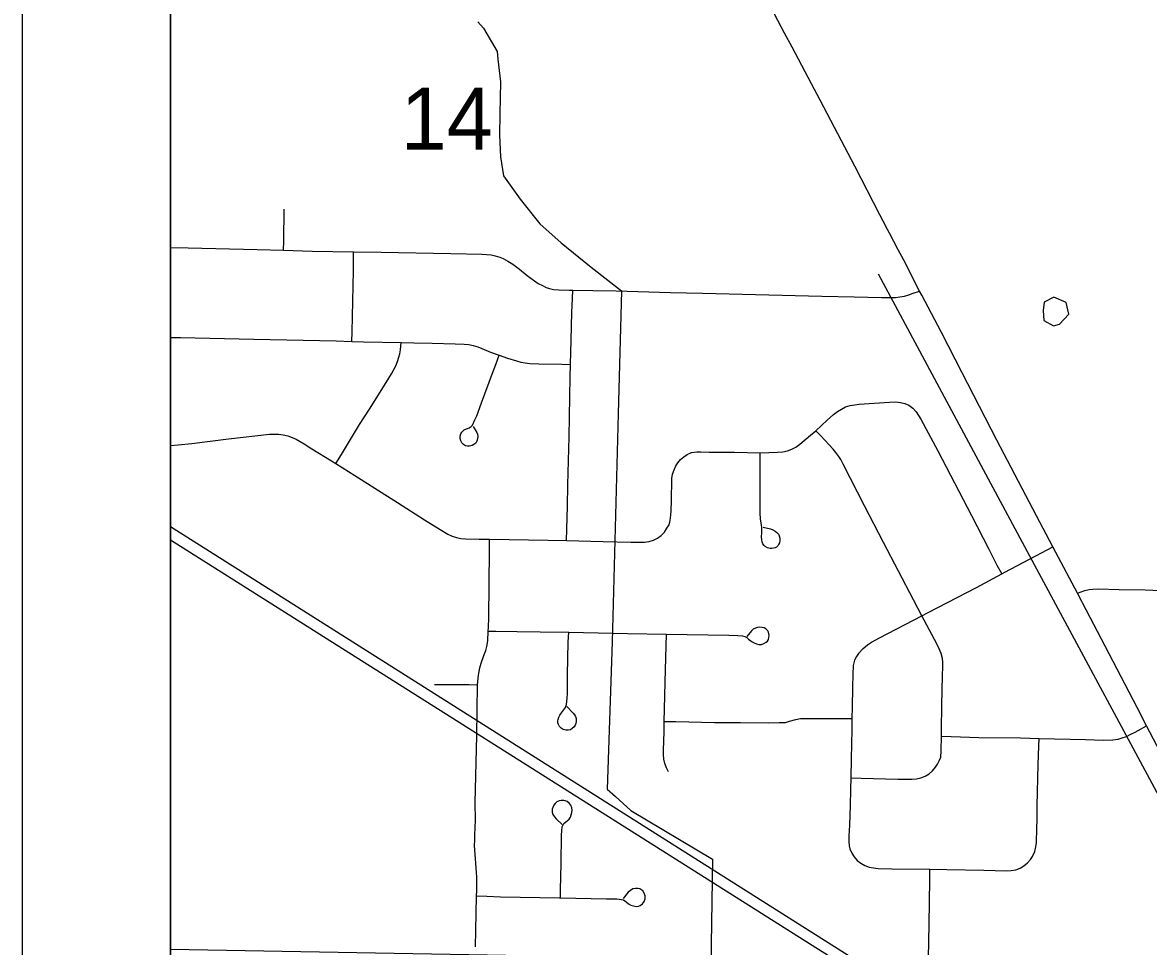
# Model space of a CAD drawing. Extents: x -59 to 43, y 0 to 22.
# Drawn here: x 23.417 to 24.177, y 18.366 to 18.99 of the extents above; entities that cross this region are included whole.
import ezdxf

# ---------------------------------------------------------------- set-up
doc = ezdxf.new("R2010")
doc.units = 0
for name, color, linetype in [('Default', 7, 'Continuous'), ('GM_X_City_Street', 7, 'Continuous'), ('GM_X_Interchange_Ramps', 7, 'Continuous'), ('GM_X_Minor_Lake', 7, 'Continuous'), ('GM_X_Minor_River', 7, 'Continuous'), ('GM_X_Rail_Line', 7, 'Continuous'), ('GM_X_Section_Text', 7, 'Continuous'), ('GM_X_State_Route', 7, 'Continuous'), ('SH_Data', 7, 'Continuous')]:
    doc.layers.add(name, color=color, linetype=linetype)

msp = doc.modelspace()

# ---------------------------------------------------------------- linework, layer by layer
at = {"layer": 'Default'}
msp.add_lwpolyline([(23.51667, 19.36712), (23.51667, 18.36457), (24.19635, 18.35229), (24.21701, 19.34715)], close=True, dxfattribs=at)
at = {"layer": 'GM_X_City_Street'}
for points in [[(23.59295, 18.83648), (23.59318, 18.84279), (23.59348, 18.86431)], [(23.51667, 18.83829), (23.52864, 18.83805), (23.57518, 18.83695), (23.59295, 18.83648), (23.6124, 18.83596), (23.64027, 18.83547), (23.65895, 18.83513), (23.70594, 18.83439), (23.72701, 18.83376), (23.73018, 18.83366), (23.73315, 18.83334), (23.73601, 18.83271), (23.73908, 18.83186), (23.74141, 18.83081), (23.74448, 18.82922), (23.74797, 18.8271), (23.75242, 18.82382), (23.75754, 18.81953), (23.76244, 18.81573), (23.76507, 18.81409), (23.76786, 18.81273), (23.77043, 18.81134), (23.77276, 18.8106), (23.77541, 18.80997), (23.7789, 18.80965), (23.78605, 18.8095), (23.78836, 18.80947), (23.80187, 18.80934), (23.81775, 18.80903), (23.85431, 18.80798), (23.87602, 18.80747), (23.9567, 18.80543), (23.97842, 18.80502), (23.99705, 18.80454), (24.00325, 18.80453), (24.00634, 18.80465), (24.00942, 18.80495), (24.01246, 18.80555), (24.01544, 18.80644), (24.01836, 18.80747), (24.02264, 18.80897)], [(23.63919, 18.77493), (23.63933, 18.78133), (23.64027, 18.8228), (23.64027, 18.82919), (23.64027, 18.83547)], [(23.7842, 18.64039), (23.78442, 18.64814), (23.78486, 18.66372), (23.78506, 18.67814), (23.78589, 18.71045), (23.78658, 18.75092), (23.78682, 18.75944), (23.78728, 18.77584), (23.78779, 18.79453), (23.78814, 18.80388), (23.78836, 18.80947)], [(23.51667, 18.77761), (23.52345, 18.77746), (23.57291, 18.77644), (23.62855, 18.77527), (23.63919, 18.77493), (23.64709, 18.77467), (23.67256, 18.7742), (23.6811, 18.77404), (23.69347, 18.77378), (23.70892, 18.77331), (23.7151, 18.77311), (23.71817, 18.77275), (23.72119, 18.77212), (23.72414, 18.77127), (23.72704, 18.77022), (23.73272, 18.76775), (23.73869, 18.76562), (23.74437, 18.76359), (23.75027, 18.76173), (23.75327, 18.761), (23.75629, 18.76044), (23.75933, 18.75999), (23.76551, 18.75969), (23.78097, 18.75951), (23.78682, 18.75944)], [(23.62823, 18.69245), (23.63207, 18.69864), (23.64424, 18.71875), (23.65101, 18.72922), (23.65941, 18.74235), (23.66585, 18.75303), (23.66877, 18.75852), (23.67, 18.76137), (23.67095, 18.76435), (23.67155, 18.76659), (23.6719, 18.76922), (23.67256, 18.7742)], [(23.72109, 18.71746), (23.7235, 18.71345), (23.72399, 18.71226), (23.7242, 18.71071), (23.72405, 18.70906), (23.7236, 18.70755), (23.7228, 18.70625), (23.72165, 18.7052), (23.7204, 18.70455), (23.7187, 18.7041), (23.71725, 18.70415), (23.71585, 18.7045), (23.71455, 18.70524), (23.71339, 18.70635), (23.7127, 18.70775), (23.71229, 18.7093), (23.71229, 18.7109), (23.71274, 18.7124), (23.71351, 18.71359), (23.71409, 18.71425), (23.71509, 18.7151), (23.71654, 18.71595), (23.71845, 18.71665), (23.71964, 18.71736), (23.72074, 18.71836), (23.72227, 18.7219), (23.72352, 18.72468), (23.72662, 18.73339), (23.73418, 18.75356), (23.73633, 18.75931), (23.73869, 18.76562)], [(23.91505, 18.69978), (23.92664, 18.70024), (23.93035, 18.70034), (23.93353, 18.70098), (23.93638, 18.70215), (23.93903, 18.70353), (23.94167, 18.70543), (23.94909, 18.71158), (23.95247, 18.71444), (23.9603, 18.72164), (23.96453, 18.72566), (23.96718, 18.72757), (23.96983, 18.72916), (23.97268, 18.73064), (23.97581, 18.73156), (23.97885, 18.73215), (23.98192, 18.73251), (24.00243, 18.73394), (24.00656, 18.73405), (24.00984, 18.73373), (24.01281, 18.73299), (24.01535, 18.73183), (24.018, 18.72992), (24.02033, 18.72728), (24.02351, 18.72241), (24.03495, 18.70103), (24.05763, 18.65742), (24.06939, 18.63466), (24.07479, 18.62387), (24.07829, 18.61804)], [(23.51667, 18.7046), (23.52187, 18.70499), (23.53115, 18.70592), (23.55578, 18.70914), (23.58351, 18.71219), (23.5866, 18.71232), (23.5897, 18.7122), (23.59278, 18.7118), (23.5958, 18.71112), (23.59873, 18.71012), (23.60155, 18.70882), (23.60693, 18.70574), (23.61213, 18.70236), (23.62532, 18.69424), (23.62823, 18.69245), (23.64107, 18.68431), (23.66989, 18.66607), (23.68823, 18.65446), (23.69871, 18.64784), (23.70404, 18.64464), (23.70683, 18.64331), (23.70978, 18.6424), (23.71283, 18.64189), (23.71593, 18.64164), (23.72522, 18.64139), (23.73203, 18.64128), (23.77173, 18.64064), (23.7842, 18.64039), (23.80894, 18.6399), (23.82753, 18.63943), (23.83683, 18.6393), (23.8399, 18.63972), (23.84285, 18.64068), (23.8456, 18.6421), (23.84808, 18.64395), (23.85026, 18.64615), (23.85203, 18.6487), (23.85344, 18.65114), (23.85428, 18.654), (23.85471, 18.65749), (23.85492, 18.66099), (23.85502, 18.66702), (23.85541, 18.68237), (23.85585, 18.68534), (23.85692, 18.68809), (23.85808, 18.69095), (23.85935, 18.69296), (23.86125, 18.69519), (23.86347, 18.69709), (23.8657, 18.69857), (23.86856, 18.69985), (23.87215, 18.70037), (23.8748, 18.70037), (23.88062, 18.70006), (23.88804, 18.70006), (23.89767, 18.70018), (23.91505, 18.69978)], [(23.9763, 18.4802), (23.98319, 18.47996), (24.00808, 18.4794), (24.0143, 18.47919), (24.01741, 18.47919), (24.02051, 18.47947), (24.02354, 18.48015), (24.02645, 18.48127), (24.0291, 18.48288), (24.03143, 18.48493), (24.03342, 18.48733), (24.03473, 18.48935), (24.036, 18.49157), (24.03695, 18.49411), (24.03727, 18.49845), (24.03741, 18.50825), (24.03748, 18.51264), (24.03768, 18.52916), (24.0382, 18.54938), (24.0383, 18.5552), (24.0383, 18.55838), (24.03809, 18.56082), (24.03724, 18.5642), (24.03586, 18.56734), (24.03452, 18.57015), (24.02576, 18.58664), (24.02419, 18.58968), (24.01862, 18.60046), (23.99838, 18.63905), (23.98545, 18.66389), (23.97112, 18.69206), (23.96942, 18.69513), (23.96815, 18.69725), (23.96603, 18.6999), (23.96423, 18.70222), (23.95588, 18.71106), (23.95247, 18.71444)], [(23.91699, 18.64939), (23.92191, 18.64835), (23.92359, 18.6477), (23.92518, 18.64686), (23.92632, 18.64597), (23.92727, 18.64482), (23.92787, 18.64373), (23.92816, 18.64214), (23.92821, 18.6403), (23.92797, 18.63901), (23.92742, 18.63777), (23.92688, 18.63683), (23.92603, 18.63608), (23.92519, 18.63553), (23.92399, 18.63519), (23.9229, 18.63508), (23.92166, 18.63508), (23.91992, 18.63553), (23.91843, 18.63642), (23.91759, 18.63717), (23.91684, 18.63826), (23.91639, 18.63956), (23.9161, 18.64094), (23.91595, 18.64293), (23.91614, 18.64561), (23.91615, 18.64935), (23.91566, 18.65231), (23.91528, 18.65479), (23.91507, 18.65913), (23.91506, 18.66929), (23.91505, 18.69978)], [(23.72271, 18.36614), (23.72307, 18.3885), (23.72343, 18.40061), (23.72354, 18.40397), (23.72353, 18.41312), (23.72306, 18.41944), (23.72201, 18.43454), (23.72211, 18.43803), (23.72211, 18.4418), (23.72266, 18.45152), (23.72256, 18.46341), (23.72349, 18.50879), (23.7241, 18.54306), (23.7247, 18.54945), (23.72554, 18.55455), (23.72639, 18.55766), (23.72837, 18.56275), (23.72969, 18.56625), (23.73035, 18.56879), (23.73092, 18.57266), (23.73131, 18.57924), (23.73148, 18.582), (23.73166, 18.58832), (23.73221, 18.6338), (23.73203, 18.64128)], [(23.98151, 18.56413), (23.98458, 18.56763), (23.98754, 18.56996), (23.99013, 18.57178), (23.99551, 18.57478), (24.02419, 18.58968), (24.02839, 18.59187), (24.06121, 18.60863), (24.07829, 18.61804), (24.08034, 18.61914), (24.10494, 18.63207), (24.11276, 18.63618)], [(24.12929, 18.60491), (24.13438, 18.60677), (24.1372, 18.60746), (24.1396, 18.60768), (24.14328, 18.60776), (24.15755, 18.60742), (24.17497, 18.60705), (24.19053, 18.60653), (24.1982, 18.60631)], [(23.73131, 18.57924), (23.73646, 18.57919), (23.75092, 18.57905), (23.76644, 18.57883), (23.78566, 18.57852), (23.82541, 18.57771), (23.85174, 18.57724), (23.86577, 18.57699), (23.89375, 18.57662), (23.89993, 18.57641), (23.90299, 18.576), (23.90461, 18.5756), (23.90586, 18.5749), (23.90708, 18.57388), (23.90856, 18.57281), (23.90967, 18.57202), (23.91103, 18.57133), (23.91242, 18.57067), (23.91415, 18.57035), (23.91588, 18.57035), (23.91745, 18.57084), (23.91913, 18.57183), (23.91991, 18.57257), (23.92053, 18.57372), (23.92089, 18.57487), (23.92102, 18.57631), (23.92093, 18.57746), (23.92065, 18.57853), (23.92007, 18.57951), (23.91879, 18.58079), (23.91764, 18.58144), (23.91629, 18.58182), (23.91468, 18.58198), (23.9132, 18.58181), (23.91177, 18.58136), (23.91024, 18.58049), (23.90901, 18.57951), (23.90593, 18.57573)], [(23.7844, 18.52833), (23.78874, 18.52378), (23.78961, 18.52274), (23.79018, 18.52166), (23.79065, 18.52031), (23.79074, 18.51844), (23.79052, 18.51697), (23.79, 18.5158), (23.78927, 18.51459), (23.78805, 18.51341), (23.78684, 18.51272), (23.78537, 18.51233), (23.78363, 18.51233), (23.78189, 18.51289), (23.78055, 18.51376), (23.77938, 18.51493), (23.77873, 18.51623), (23.77834, 18.51736), (23.7783, 18.51861), (23.77843, 18.51966), (23.77894, 18.52117), (23.77968, 18.5226), (23.78068, 18.52417), (23.78341, 18.52776), (23.78419, 18.52963), (23.78457, 18.534), (23.78474, 18.53715), (23.78486, 18.54979), (23.78537, 18.57188), (23.78566, 18.57852)], [(23.85303, 18.48425), (23.8516, 18.48695), (23.85057, 18.48983), (23.84995, 18.49282), (23.84968, 18.49586), (23.84967, 18.49893), (23.8501, 18.51117), (23.8502, 18.51825), (23.85032, 18.52647), (23.85073, 18.54483), (23.85149, 18.5693), (23.85174, 18.57724)], [(23.98151, 18.56413), (23.98008, 18.56214), (23.97881, 18.5596), (23.97782, 18.556), (23.97754, 18.55018), (23.97733, 18.54118), (23.97702, 18.52784), (23.97682, 18.52032), (23.97682, 18.51281), (23.97651, 18.49311), (23.9763, 18.4802), (23.97599, 18.47236), (23.97567, 18.46156), (23.97536, 18.44822), (23.97495, 18.44102), (23.97484, 18.43721), (23.97516, 18.43435), (23.97566, 18.43223), (23.97694, 18.42941), (23.97853, 18.42674), (23.98056, 18.42442), (23.98296, 18.42245), (23.98563, 18.42089), (23.98855, 18.41985), (23.9916, 18.41932), (23.99469, 18.41904), (24.00398, 18.41874), (24.0296, 18.41847), (24.04118, 18.41834), (24.06597, 18.41779), (24.08147, 18.41746), (24.08457, 18.41759), (24.08762, 18.41813), (24.09052, 18.41919), (24.09319, 18.42075), (24.0956, 18.4227), (24.09767, 18.42501), (24.09897, 18.42712), (24.1005, 18.4305), (24.1013, 18.43349), (24.10161, 18.43657), (24.10187, 18.44587), (24.10207, 18.45206), (24.10203, 18.46136), (24.10267, 18.48925), (24.1032, 18.50164), (24.10343, 18.5068)], [(23.69506, 18.54326), (23.70391, 18.54316), (23.7184, 18.54314), (23.7241, 18.54306)], [(23.8502, 18.51825), (23.85799, 18.51816), (23.88414, 18.51764), (23.90159, 18.51748), (23.9203, 18.51744), (23.92787, 18.51756), (23.932, 18.51767), (23.93486, 18.51841), (23.93898, 18.51968), (23.94216, 18.52021), (23.94713, 18.5202), (23.96064, 18.52015), (23.96905, 18.52023), (23.97682, 18.52032)], [(24.03741, 18.50825), (24.04397, 18.50806), (24.06273, 18.50752), (24.09088, 18.50711), (24.10343, 18.5068), (24.13469, 18.50604), (24.14691, 18.50565), (24.15316, 18.50587), (24.15675, 18.5064), (24.15951, 18.50714), (24.16236, 18.50809), (24.16545, 18.50961), (24.16821, 18.51109), (24.17599, 18.51527)], [(23.7801, 18.39911), (23.78018, 18.40426), (23.78051, 18.42247), (23.78079, 18.44136), (23.78103, 18.44449), (23.78128, 18.44713), (23.78182, 18.44842), (23.78242, 18.44932), (23.78598, 18.45234), (23.78675, 18.45355), (23.78739, 18.45513), (23.78784, 18.45679), (23.78799, 18.45828), (23.78784, 18.45987), (23.78714, 18.46166), (23.78605, 18.46301), (23.78455, 18.4641), (23.78331, 18.4646), (23.78224, 18.46482), (23.78053, 18.46494), (23.77915, 18.4646), (23.77769, 18.46394), (23.77656, 18.46291), (23.7756, 18.46181), (23.77493, 18.46021), (23.77455, 18.45902), (23.77453, 18.45711), (23.77501, 18.45539), (23.776, 18.4538), (23.77707, 18.45257), (23.78113, 18.44857)], [(24.02872, 18.35333), (24.02879, 18.35839), (24.0291, 18.38136), (24.0295, 18.41121), (24.0296, 18.41847)], [(23.72343, 18.40061), (23.73023, 18.40028), (23.73945, 18.39984), (23.77948, 18.39912), (23.7801, 18.39911), (23.81107, 18.39853), (23.81824, 18.39838), (23.82138, 18.3981), (23.82264, 18.3977), (23.82435, 18.39652), (23.82604, 18.39509), (23.82758, 18.39424), (23.82949, 18.39365), (23.83124, 18.39339), (23.83273, 18.3936), (23.834, 18.39403), (23.83549, 18.39515), (23.83665, 18.39669), (23.83718, 18.39854), (23.83718, 18.40056), (23.83665, 18.40237), (23.8357, 18.40385), (23.83378, 18.40512), (23.83225, 18.40549), (23.83076, 18.40555), (23.82906, 18.40513), (23.82747, 18.40411), (23.82588, 18.40289), (23.82249, 18.39864)]]:
    msp.add_lwpolyline(points, dxfattribs=at)
at = {"layer": 'GM_X_Interchange_Ramps'}
msp.add_lwpolyline([(23.51667, 20.9), (23.51667, 15.35309)], dxfattribs=at)
at = {"layer": 'GM_X_Minor_Lake'}
msp.add_line((24.10691, 18.80153), (24.10605, 18.79585), dxfattribs=at)
msp.add_lwpolyline([(24.10605, 18.79585), (24.10668, 18.78899), (24.11306, 18.78545), (24.11725, 18.78651), (24.12345, 18.79324), (24.1217, 18.80125), (24.11343, 18.80483), (24.10691, 18.80153)], dxfattribs=at)
at = {"layer": 'GM_X_Minor_River'}
for points in [[(23.72431, 18.99082), (23.72802, 18.98656), (23.73721, 18.97081), (23.73786, 18.96547), (23.73947, 18.95024), (23.73906, 18.92858), (23.73879, 18.91414), (23.73965, 18.89968), (23.74168, 18.88672), (23.75276, 18.87092), (23.7661, 18.85433), (23.78065, 18.84151), (23.80083, 18.82516), (23.82139, 18.80919), (23.81905, 18.72599), (23.81499, 18.57213), (23.81158, 18.4726), (23.81717, 18.46756), (23.82762, 18.45824), (23.88276, 18.42527), (23.8815, 18.33901), (23.88001, 18.22082), (23.8796, 18.11934)], [(24.23865, 18.36726), (24.0972, 18.62991), (23.99498, 18.82037)]]:
    msp.add_lwpolyline(points, dxfattribs=at)
at = {"layer": 'GM_X_Rail_Line'}
for points in [[(24.85953, 17.57035), (24.84019, 17.76617), (24.82935, 17.81016), (24.79303, 17.84892), (24.19874, 18.21842), (23.51667, 18.64966)], [(23.51667, 18.64098), (24.21418, 18.20034), (24.75495, 17.86208), (24.75829, 17.57829), (24.85953, 17.57035)]]:
    msp.add_lwpolyline(points, dxfattribs=at)
at = {"layer": 'GM_X_State_Route'}
for points in [[(23.93653, 18.9736), (23.93146, 18.98314), (23.92022, 19.00445), (23.91405, 19.01614)], [(24.00239, 18.84794), (24.00106, 18.85049), (23.99806, 18.85624), (23.99592, 18.8604), (23.97897, 18.89334), (23.97002, 18.91041), (23.95547, 18.93794), (23.94969, 18.94885), (23.93653, 18.9736)], [(24.13274, 18.59839), (24.13228, 18.59928), (24.12929, 18.60491), (24.11472, 18.63245), (24.11276, 18.63618), (24.10167, 18.65721), (24.07494, 18.70815), (24.05147, 18.75378), (24.03717, 18.7814), (24.0241, 18.80614), (24.02264, 18.80897), (24.01192, 18.82969), (24.00817, 18.83686), (24.00239, 18.84794)], [(24.1957, 18.47781), (24.18757, 18.4931), (24.17599, 18.51527), (24.16956, 18.52759), (24.14808, 18.56904), (24.13274, 18.59839)]]:
    msp.add_lwpolyline(points, dxfattribs=at)
at = {"layer": 'SH_Data'}
for points in [[(23.41667, 21), (30.41667, 21), (30.41667, 14), (23.41667, 14)], [(23.51667, 20.9), (30.31667, 20.9), (30.31667, 14.1), (23.51667, 14.1)]]:
    msp.add_lwpolyline(points, close=True, dxfattribs=at)

# ---------------------------------------------------------------- texts
at = {"layer": 'GM_X_Section_Text'}
msp.add_text('14', height=0.041856, rotation=0.00001, dxfattribs=at).set_placement((23.67214, 18.90447))

doc.saveas('drawing.dxf')
